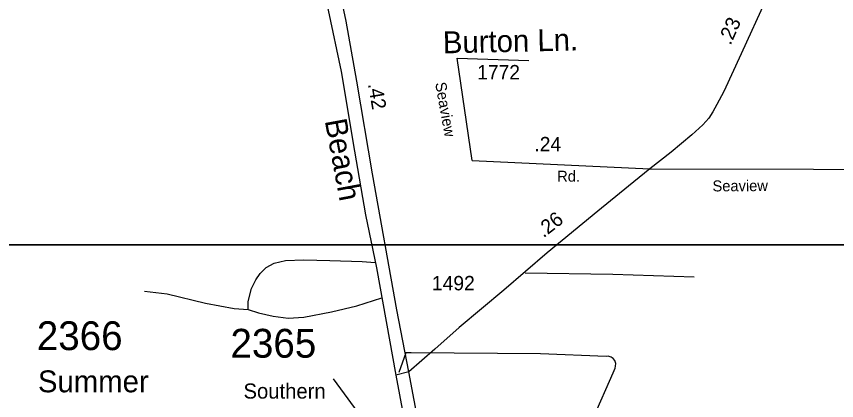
# Model space of a CAD drawing. Extents: x 2290055 to 2389491, y 66597 to 237875.
# Drawn here: x 2332508 to 2336063, y 125120 to 126787 of the extents above; entities that cross this region are included whole.
import ezdxf

# ---------------------------------------------------------------- set-up
doc = ezdxf.new("R2010")
doc.units = 0
for name, color, linetype in [('Exist Road Non-System Type 51', 7, 'Continuous'), ('Exist Road Non-System Type 51 Label', 7, 'Continuous'), ('Exist Road Primary US Divided Attributed', 7, 'Continuous'), ('Exist Road Primary US Label', 7, 'Continuous'), ('Exist Road Primary US Mileage Hundredths English Label', 7, 'Continuous'), ('Exist Road Secondary Mileage Hundredths English Label', 7, 'Continuous'), ('Exist Road Secondary Type 51 Attributed', 7, 'Continuous'), ('Exist Road Secondary Type 51 Label', 7, 'Continuous'), ('Exist Road Secondary Type 51 Number Label', 7, 'Continuous'), ('Map Preparation Inset Cut Line', 7, 'Continuous')]:
    doc.layers.add(name, color=color, linetype=linetype)

msp = doc.modelspace()

# ---------------------------------------------------------------- linework, layer by layer
at = {"layer": 'Exist Road Non-System Type 51'}
for p, q in [((2334196, 125326.8), (2334165, 125242.4)), ((2334218.9, 125326.6), (2334196, 125326.8))]:
    msp.add_line(p, q, dxfattribs=at)
for points in [[(2334417.9, 126605.1), (2334728.5, 126595.6)], [(2333511.7, 125515.9), (2333511.7, 125549.9), (2333526.7, 125606.6), (2333545.6, 125644.3), (2333564.5, 125670.8), (2333590.9, 125697.2), (2333624.9, 125716.1), (2333673.9, 125727.4), (2333753.2, 125731.2), (2333866.4, 125727.4), (2334006.1, 125723.6), (2334063.2, 125719.4)], [(2334712.4, 125674.3), (2335092.6, 125668.1), (2335444.9, 125657.7)], [(2333062.5, 125595.2), (2333160.7, 125583.9), (2333326.7, 125542.4), (2333451.3, 125519.7), (2333511.7, 125515.9)], [(2333511.7, 125515.9), (2333556.9, 125500.8), (2333621.1, 125485.7), (2333685.3, 125478.2), (2333753.2, 125482), (2333874, 125504.6), (2333983.4, 125531.1), (2334091.3, 125565.9)], [(2334885.5, 124788.2), (2335008.9, 125047.1), (2335095.1, 125240.2), (2335102.8, 125260.2), (2335104.8, 125270.1), (2335105.3, 125281.6), (2335101.5, 125293.6), (2335094.3, 125302.2), (2335086.2, 125307.8), (2335072.9, 125312.2), (2335064.4, 125311.8), (2334780, 125322.9), (2334218.9, 125326.6)]]:
    msp.add_lwpolyline(points, dxfattribs=at)
at = {"layer": 'Exist Road Primary US Divided Attributed'}
for points in [[(2333727.2, 127401), (2333771.5, 127251.8), (2333791.4, 127174.5), (2333859.6, 126813.3), (2333915.5, 126547.3), (2333973.8, 126202), (2334020.6, 125925.8), (2334067.9, 125696.5), (2334151.7, 125229.8)], [(2334208.5, 125244.8), (2334156.7, 125514), (2334050.8, 126103.8), (2333983.2, 126505.3), (2333936.5, 126766.6), (2333906.2, 126911.3), (2333887.6, 127009.2), (2333845.6, 127212.2), (2333815.3, 127319.6), (2333786.7, 127419.2)], [(2334151.7, 125229.8), (2334232.3, 124804.2), (2334264.7, 124592.3), (2334296.6, 124275), (2334345.9, 124001.6)], [(2334404.6, 124008.1), (2334355.6, 124294.9), (2334352.8, 124473.9), (2334274, 124898.9), (2334208.5, 125244.8)]]:
    msp.add_lwpolyline(points, dxfattribs=at)
at = {"layer": 'Exist Road Secondary Type 51 Attributed'}
for points in [[(2335924.8, 127235), (2335757.7, 126863.6), (2335649.1, 126624.2), (2335574.5, 126460.5), (2335544.2, 126404.6), (2335526, 126373.4), (2335508.7, 126344.8), (2335482.7, 126316.2), (2335435.9, 126273.3), (2335345.8, 126198), (2335253.7, 126125.8)], [(2334482.7, 126162.4), (2334417.9, 126605.1)], [(2334482.7, 126162.4), (2335253.7, 126125.8)], [(2335253.7, 126125.8), (2335161.4, 126050.4), (2335027.9, 125942.4), (2334807.8, 125760.9), (2334620.9, 125599.3), (2334426.9, 125437.4), (2334321.8, 125343.3), (2334208.5, 125244.8)], [(2335253.7, 126125.8), (2335962.5, 126123.5), (2336500.8, 126120.8), (2337229.4, 126112.8), (2337944.5, 126110.1)], [(2334208.5, 125244.8), (2334151.7, 125229.8)]]:
    msp.add_lwpolyline(points, dxfattribs=at)
at = {"layer": 'Exist Road Secondary Type 51 Number Label'}
msp.add_lwpolyline([(2334048.6, 124640.4), (2334020.8, 125024.8), (2333881.8, 125214.6)], dxfattribs=at)
at = {"layer": 'Map Preparation Inset Cut Line'}
for points in [[(2326073, 125795.4), (2326049.1, 134004.6), (2335243.2, 134004.6), (2335243.2, 141886.2), (2343900.4, 141886.2), (2341393.8, 134004.6), (2339225, 125795.4)], [(2341393.8, 134004.6), (2335243.2, 134004.6), (2326049.1, 134004.6), (2326073, 125795.4), (2339225, 125795.4)]]:
    msp.add_lwpolyline(points, close=True, dxfattribs=at)

# ---------------------------------------------------------------- texts
at = {"layer": 'Exist Road Non-System Type 51 Label'}
msp.add_text('Burton Ln.', height=95, rotation=1.273, dxfattribs=at).set_placement((2334357.2, 126626.4))
at = {"layer": 'Exist Road Primary US Label'}
msp.add_text('Beach', height=95, rotation=280.5302, dxfattribs=at).set_placement((2333843.8, 126334.7))
at = {"layer": 'Exist Road Primary US Mileage Hundredths English Label'}
msp.add_text('.42', height=62.5, rotation=279.5607, dxfattribs=at).set_placement((2334031.3, 126493.4))
at = {"layer": 'Exist Road Secondary Mileage Hundredths English Label'}
for s, rotation, p in [('.23', 66.2103, (2335603.3, 126658.9)), ('.24', 359.6658, (2334752.6, 126201.8)), ('.26', 37.9424, (2334792.5, 125824.1))]:
    msp.add_text(s, height=62.5, rotation=rotation, dxfattribs=at).set_placement(p)
at = {"layer": 'Exist Road Secondary Type 51 Label'}
for s, rotation, p in [('Seaview', 280.2118, (2334322.6, 126497.4)), ('Rd.', 0.3162, (2334851.9, 126069.6)), ('Seaview', 0.3925, (2335525.2, 126027.5))]:
    msp.add_text(s, height=47.5, rotation=rotation, dxfattribs=at).set_placement(p)
for s, height, p in [('Summer', 95, (2332600.9, 125156)), ('Southern', 65.62, (2333492, 125128.7))]:
    msp.add_text(s, height=height, dxfattribs=at).set_placement(p)
at = {"layer": 'Exist Road Secondary Type 51 Number Label'}
for s, height, p in [('1772', 62.5, (2334504.7, 126513.6)), ('1492', 62.5, (2334308.7, 125598.4)), ('2366', 125, (2332596, 125339.1)), ('2365', 125, (2333435.5, 125306.3))]:
    msp.add_text(s, height=height, dxfattribs=at).set_placement(p)

doc.saveas('drawing.dxf')
